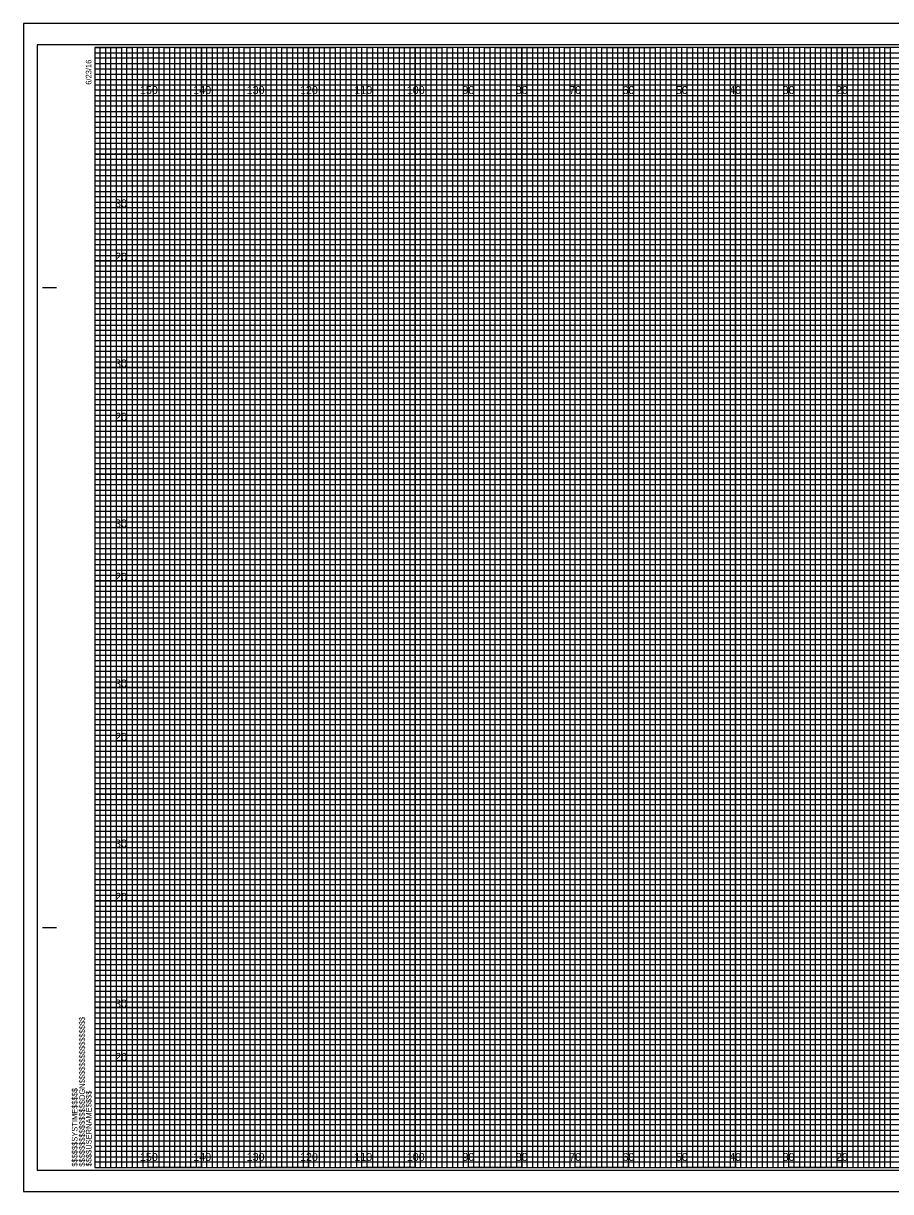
# Model space of a CAD drawing. Extents: x -13 to 323, y 1096 to 1314.
# Drawn here: x -13.4 to 149.1, y 1095.5 to 1314.5 of the extents above; entities that cross this region are included whole.
import ezdxf

# ---------------------------------------------------------------- set-up
doc = ezdxf.new("R2010")
doc.units = 0
for name, color, linetype in [('Prop XS Offset Labels', 7, 'Continuous'), ('Prop XS Station Labels', 7, 'Continuous'), ('Sheet Cross Section CELL', 7, 'Continuous'), ('Sheet Cross Section Grid Major CELL', 7, 'Continuous'), ('Sheet Cross Section Grid Middle CELL', 7, 'Continuous'), ('Sheet Cross Section Grid Minor 1 CELL', 7, 'Continuous'), ('Sheet Cross Section Grid Minor 2 CELL', 7, 'Continuous'), ('Sheet Cutting Line CELL', 7, 'Continuous'), ('Sheet DOT Grid CELL', 7, 'Continuous'), ('Sheet Plot Border Inside CELL', 7, 'Continuous'), ('Sheet Plot Border Outside CELL', 7, 'Continuous')]:
    doc.layers.add(name, color=color, linetype=linetype)

msp = doc.modelspace()

# ---------------------------------------------------------------- linework, layer by layer
at = {"layer": 'Sheet Cross Section CELL'}
for p, q in [((-9.8, 1265), (-7.3, 1265)), ((-9.7, 1265), (-7.2, 1265)), ((-9.8, 1145), (-7.3, 1145)), ((-9.7, 1145), (-7.2, 1145)), ((0, 1100), (0, 1100)), ((0, 1100), (0, 1100)), ((0, 1100), (0, 1100)), ((0, 1100), (0, 1100)), ((0, 1100), (0, 1100)), ((0, 1100), (0, 1100)), ((0, 1100), (0, 1100))]:
    msp.add_line(p, q, dxfattribs=at)
msp.add_lwpolyline([(320, 1310), (0, 1310), (0, 1100), (320, 1100)], close=True, dxfattribs=at)
at = {"layer": 'Sheet Cross Section Grid Major CELL'}
for p, q in [((10, 1310), (0, 1310)), ((10, 1100), (10, 1310)), ((30, 1310), (20, 1310)), ((20, 1310), (20, 1100)), ((30, 1100), (30, 1310)), ((50, 1310), (40, 1310)), ((40, 1310), (40, 1100)), ((50, 1100), (50, 1310)), ((70, 1310), (60, 1310)), ((60, 1310), (60, 1100)), ((70, 1100), (70, 1310)), ((90, 1310), (80, 1310)), ((80, 1310), (80, 1100)), ((90, 1100), (90, 1310)), ((110, 1310), (100, 1310)), ((100, 1310), (100, 1100)), ((110, 1100), (110, 1310)), ((130, 1310), (120, 1310)), ((120, 1310), (120, 1100)), ((130, 1100), (130, 1310)), ((150, 1310), (140, 1310)), ((140, 1310), (140, 1100)), ((20, 1100), (10, 1100)), ((40, 1100), (30, 1100)), ((60, 1100), (50, 1100)), ((80, 1100), (70, 1100)), ((100, 1100), (90, 1100)), ((120, 1100), (110, 1100)), ((140, 1100), (130, 1100))]:
    msp.add_line(p, q, dxfattribs=at)
for points in [[(0, 1300), (320, 1300), (320, 1290), (0, 1290)], [(0, 1280), (320, 1280), (320, 1270), (0, 1270)], [(0, 1260), (320, 1260), (320, 1250), (0, 1250)], [(0, 1240), (320, 1240), (320, 1230), (0, 1230)], [(0, 1220), (320, 1220), (320, 1210), (0, 1210)], [(0, 1200), (320, 1200), (320, 1190), (0, 1190)], [(0, 1180), (320, 1180), (320, 1170), (0, 1170)], [(0, 1160), (320, 1160), (320, 1150), (0, 1150)], [(0, 1140), (320, 1140), (320, 1130), (0, 1130)], [(0, 1120), (320, 1120), (320, 1110), (0, 1110)]]:
    msp.add_lwpolyline(points, dxfattribs=at)
at = {"layer": 'Sheet Cross Section Grid Middle CELL'}
for points in [[(0, 1310), (5, 1310), (5, 1100), (15, 1100), (15, 1310), (25, 1310), (25, 1100), (35, 1100), (35, 1310), (45, 1310), (45, 1100), (55, 1100), (55, 1310), (65, 1310), (65, 1100), (75, 1100), (75, 1310), (85, 1310), (85, 1100), (95, 1100), (95, 1310), (105, 1310), (105, 1100), (115, 1100), (115, 1310), (125, 1310), (125, 1100), (135, 1100), (135, 1310), (145, 1310), (145, 1100), (155, 1100)], [(0, 1305), (275, 1305)], [(0, 1285), (320, 1285), (320, 1295), (0, 1295)], [(0, 1265), (320, 1265), (320, 1275), (0, 1275)], [(0, 1245), (320, 1245), (320, 1255), (0, 1255)], [(0, 1225), (320, 1225), (320, 1235), (0, 1235)], [(0, 1205), (320, 1205), (320, 1215), (0, 1215)], [(0, 1185), (320, 1185), (320, 1195), (0, 1195)], [(0, 1165), (320, 1165), (320, 1175), (0, 1175)], [(0, 1145), (320, 1145), (320, 1155), (0, 1155)], [(0, 1125), (320, 1125), (320, 1135), (0, 1135)], [(0, 1105), (320, 1105), (320, 1115), (0, 1115)]]:
    msp.add_lwpolyline(points, dxfattribs=at)
at = {"layer": 'Sheet Cross Section Grid Minor 1 CELL'}
for p, q in [((0, 1309), (260, 1309)), ((260, 1307.98), (0, 1307.98)), ((0, 1307.98), (0, 1307)), ((0, 1307), (260, 1307)), ((260, 1305.89), (0, 1305.89)), ((0, 1305.89), (0, 1304)), ((0, 1304), (320, 1304))]:
    msp.add_line(p, q, dxfattribs=at)
for points in [[(0, 1303), (270, 1303), (320, 1303), (320, 1302), (0, 1302)], [(0, 1301), (320, 1301), (320, 1299), (0, 1299)], [(0, 1298), (320, 1298), (320, 1297), (0, 1296.98)], [(0, 1296), (320, 1296), (320, 1294), (0, 1294)], [(0, 1293), (320, 1293), (320, 1292), (0, 1292)], [(0, 1291), (320, 1291), (320, 1289), (0, 1289)], [(0, 1288), (320, 1288), (320, 1287), (0, 1287)], [(0, 1286), (320, 1286), (320, 1284), (0, 1284)], [(0, 1283), (320, 1283), (320, 1282), (0, 1282)], [(0, 1281), (320, 1281), (320, 1279), (0, 1279)], [(0, 1278), (320, 1278), (320, 1277), (0, 1277)], [(0, 1276), (320, 1276), (320, 1273.95), (320, 1273), (320, 1272), (0, 1272)], [(0, 1274), (320, 1274), (320, 1273), (0, 1273)], [(0, 1271), (320, 1271), (320, 1269), (0, 1269.03)], [(0, 1269.03), (320, 1269), (320, 1268), (0, 1268)], [(0, 1267), (320, 1267), (320, 1266), (0, 1266)], [(0, 1264), (320, 1264), (320, 1263), (0, 1263)], [(0, 1262), (320, 1262), (320, 1261), (0, 1261)], [(-0.07, 1258.89), (320, 1258.89), (320, 1257.88), (-0.07, 1257.88)], [(0, 1257), (320, 1257), (320, 1256), (0, 1256)], [(0, 1254), (320, 1254), (320, 1253), (0, 1253)], [(0, 1252), (320, 1252), (320, 1251), (0, 1251)], [(0, 1249), (320, 1249), (320, 1248), (0, 1248)], [(0, 1247), (320, 1247), (320, 1246), (0, 1246)], [(0, 1244), (320, 1244), (320, 1243), (0, 1243)], [(0, 1242), (320, 1242), (320, 1241), (0, 1241)], [(0, 1239), (320, 1239), (319.99, 1237.98), (0, 1238)], [(0, 1237), (320, 1237), (320, 1236), (0, 1236)], [(0, 1234), (320, 1234), (320, 1233), (0, 1233)], [(0, 1232), (320, 1232), (320, 1231), (0, 1231)], [(0, 1229), (320, 1229), (320, 1228), (0, 1228)], [(0, 1227), (320, 1227), (320, 1226), (0, 1226)], [(0, 1224), (320, 1224), (320, 1223), (0, 1223)], [(0, 1222), (320, 1222), (320, 1221), (0, 1221)], [(0, 1219), (320, 1219), (320, 1218), (0, 1218)], [(0, 1216.99), (320.07, 1216.91), (320, 1216), (0, 1216)], [(0, 1214), (320, 1214), (320, 1213), (0, 1213)], [(0, 1212), (320, 1212), (320, 1211), (0, 1211)], [(0, 1209), (320, 1209), (320, 1208), (0, 1208)], [(0, 1207), (320, 1207), (320, 1206), (0, 1206)], [(0, 1204), (320, 1204), (320, 1203), (0, 1203)], [(0, 1202), (320, 1202), (320, 1201), (0, 1201)], [(0, 1199), (320, 1199), (320, 1198), (0, 1198)], [(0, 1197), (320, 1197), (320, 1196), (0, 1196)], [(0, 1194), (320, 1194), (320, 1193), (0, 1193)], [(0, 1192), (320, 1192), (320, 1191), (0, 1191)], [(0, 1189), (320, 1189), (320, 1188), (0, 1188)], [(0, 1187), (320, 1187), (320, 1186), (0, 1186)], [(0, 1184), (320, 1184), (320, 1183), (0, 1183)], [(0, 1182), (320, 1182), (320, 1181), (0, 1181)], [(0, 1179), (320, 1179), (319.99, 1177.98), (0, 1178)], [(0, 1177), (320, 1177), (320, 1176), (0, 1176)], [(0, 1174), (320, 1174), (320, 1173), (0, 1173)], [(0, 1172), (320, 1172), (320, 1171), (0, 1171)], [(0, 1169), (320, 1169), (320, 1168), (0, 1168)], [(0, 1167), (320, 1167), (320, 1166), (0, 1166)], [(0, 1164), (320, 1164), (320, 1163), (0, 1163)], [(0, 1162), (320, 1162), (320, 1161), (0, 1161)], [(0, 1159), (320, 1159), (320, 1158), (0, 1158)], [(0, 1156.99), (320.07, 1156.91), (320, 1156), (0, 1156)], [(0, 1154), (320, 1154), (320, 1153), (0, 1153)], [(0, 1152), (320, 1152), (320, 1151), (0, 1151)], [(0, 1149), (320, 1149), (320, 1148), (0, 1148)], [(0, 1147), (320, 1147), (320, 1146), (0, 1146)], [(0, 1144), (320, 1144), (320, 1143), (0, 1143)], [(0, 1142), (320, 1142), (320, 1141), (0, 1141)], [(0, 1139), (320, 1139), (320, 1138), (0, 1138)], [(0, 1137), (320, 1137), (320, 1136), (0, 1136)], [(0, 1134), (320, 1134), (320, 1133), (0, 1133)], [(0, 1132), (320, 1132), (320, 1131), (0, 1131)], [(0, 1129), (320, 1129), (320, 1128), (0, 1128)], [(0, 1127), (320, 1127), (320, 1126), (0, 1126)], [(0, 1124), (320, 1124), (320, 1123), (0, 1123)], [(0, 1122), (320, 1122), (320, 1121), (0, 1121)], [(0, 1119), (320, 1119), (320, 1118), (0, 1118)], [(0, 1117), (320, 1117), (320, 1116), (0, 1116)], [(0, 1114), (320, 1114), (320, 1113), (0, 1113)], [(0, 1112), (320, 1112), (320, 1111), (0, 1111)], [(0, 1109), (320, 1109), (320, 1108), (0, 1108)], [(0, 1107), (320, 1107), (320, 1106), (0, 1106)], [(0, 1104), (320, 1104), (320, 1103), (0, 1103)], [(0, 1102), (320, 1102), (320, 1101), (0, 1101)]]:
    msp.add_lwpolyline(points, dxfattribs=at)
at = {"layer": 'Sheet Cross Section Grid Minor 2 CELL'}
for points in [[(0, 1100), (1, 1100), (1, 1310), (2, 1310), (2, 1100)], [(2, 1100), (3, 1100), (3, 1310), (4, 1310), (4, 1100)], [(5, 1100), (6, 1100), (6, 1310), (7, 1310), (7, 1100)], [(7, 1100), (8, 1100), (8, 1310), (9, 1310), (9, 1100)], [(10, 1100), (11, 1100), (11, 1310), (12, 1310), (12, 1100)], [(12, 1100), (13, 1100), (13, 1310), (14, 1310), (14, 1100)], [(15, 1100), (16, 1100), (16, 1310), (17, 1310), (17, 1100)], [(17, 1100), (18, 1100), (18, 1310), (19, 1310), (19, 1100)], [(20, 1100), (21, 1100), (21, 1310), (22, 1310), (22, 1100)], [(22, 1100), (23, 1100), (23, 1310), (24, 1310), (24, 1100)], [(25, 1100), (26, 1100), (26, 1310), (27, 1310), (27, 1100)], [(27, 1100), (28, 1100), (28, 1310), (29, 1310), (29, 1100)], [(30, 1100), (31, 1100), (31, 1310), (32, 1310), (32, 1100)], [(32, 1100), (33, 1100), (33, 1310), (34, 1310), (34, 1100)], [(35, 1100), (36, 1100), (36, 1310), (37, 1310), (37, 1100)], [(37, 1100), (38, 1100), (38, 1310), (39, 1310), (39, 1100)], [(40, 1100), (41, 1100), (41, 1310), (42, 1310), (42, 1100)], [(42, 1100), (43, 1100), (43, 1310), (44, 1310), (44, 1100)], [(45, 1100), (46, 1100), (46, 1310), (47, 1310), (47, 1100)], [(47, 1100), (48, 1100), (48, 1310), (49, 1310), (49, 1100)], [(50, 1100), (51, 1100), (51, 1310), (52, 1310), (52, 1100)], [(52, 1100), (53, 1100), (53, 1310), (54, 1310), (54, 1100)], [(55, 1100), (56, 1100), (56, 1310), (57, 1310), (57, 1100)], [(57, 1100), (58, 1100), (58, 1310), (59, 1310), (59, 1100)], [(60, 1100), (61, 1100), (61, 1310), (62, 1310), (62, 1100)], [(62, 1100), (63, 1100), (63, 1310), (64, 1310), (64, 1100)], [(65, 1100), (66, 1100), (66, 1310), (67, 1310), (67, 1100)], [(67, 1100), (68, 1100), (68, 1310), (69, 1310), (69, 1100)], [(70, 1100), (71, 1100), (71, 1310), (72, 1310), (72, 1100)], [(72, 1100), (73, 1100), (73, 1310), (74, 1310), (74, 1100)], [(75, 1100), (76, 1100), (76, 1310), (77, 1310), (77, 1100)], [(77, 1100), (78, 1100), (78, 1310), (79, 1310), (79, 1100)], [(80, 1100), (81, 1100), (81, 1310), (82, 1310), (82, 1100)], [(82, 1100), (83, 1100), (83, 1310), (84, 1310), (84, 1100)], [(85, 1100), (86, 1100), (86, 1310), (87, 1310), (87, 1100)], [(87, 1100), (88, 1100), (88, 1310), (89, 1310), (89, 1100)], [(90, 1100), (91, 1100), (91, 1310), (92, 1310), (92, 1100)], [(92, 1100), (93, 1100), (93, 1310), (94, 1310), (94, 1100)], [(95, 1100), (96, 1100), (96, 1310), (97, 1310), (97, 1100)], [(97, 1100), (98, 1100), (98, 1310), (99, 1310), (99, 1100)], [(100, 1100), (101, 1100), (101, 1310), (102, 1310), (102, 1100)], [(102, 1100), (103, 1100), (103, 1310), (104, 1310), (104, 1100)], [(105, 1100), (106, 1100), (106, 1310), (107, 1310), (107, 1100)], [(107, 1100), (108, 1100), (108, 1310), (109, 1310), (109, 1100)], [(110, 1100), (111, 1100), (111, 1310), (112, 1310), (112, 1100)], [(112, 1100), (113, 1100), (113, 1310), (114, 1310), (114, 1100)], [(115, 1100), (116, 1100), (116, 1310), (117, 1310), (117, 1100)], [(117, 1100), (118, 1100), (118, 1310), (119, 1310), (119, 1100)], [(120, 1100), (121, 1100), (121, 1310), (122, 1310), (122, 1100)], [(122, 1100), (123, 1100), (123, 1310), (124, 1310), (124, 1100)], [(125, 1100), (126, 1100), (126, 1310), (127, 1310), (127, 1100)], [(127, 1100), (128, 1100), (128, 1310), (129, 1310), (129, 1100)], [(130, 1100), (131, 1100), (131, 1310), (132, 1310), (132, 1100)], [(132, 1100), (133, 1100), (133, 1310), (134, 1310), (134, 1100)], [(135, 1100), (136, 1100), (136, 1310), (137, 1310), (137, 1100)], [(137, 1100), (138, 1100), (138, 1310), (139, 1310), (139, 1100)], [(140, 1100), (141, 1100), (141, 1310), (142, 1310), (142, 1100)], [(142, 1100), (143, 1100), (143, 1310), (144, 1310), (144, 1100)], [(145, 1100), (146, 1100), (146, 1310), (147, 1310), (147, 1100)], [(147, 1100), (148, 1100), (148, 1310), (149, 1310), (149, 1100)]]:
    msp.add_lwpolyline(points, dxfattribs=at)
at = {"layer": 'Sheet Cutting Line CELL'}
for p, q in [((323.3, 1314.5), (-13.4, 1314.5)), ((-13.4, 1314.5), (-13.4, 1095.5)), ((-13.4, 1095.5), (323.3, 1095.5))]:
    msp.add_line(p, q, dxfattribs=at)
at = {"layer": 'Sheet DOT Grid CELL'}
for p, q in [((10, 1100), (10, 1310)), ((20, 1100), (20, 1310)), ((30, 1100), (30, 1310)), ((40, 1100), (40, 1310)), ((50, 1100), (50, 1310)), ((60, 1100), (60, 1310)), ((70, 1100), (70, 1310)), ((80, 1100), (80, 1310)), ((90, 1100), (90, 1310)), ((100, 1100), (100, 1310)), ((110, 1100), (110, 1310)), ((120, 1100), (120, 1310)), ((130, 1100), (130, 1310)), ((140, 1100), (140, 1310)), ((0, 1300), (320, 1300)), ((0, 1290), (320, 1290)), ((0, 1280), (320, 1280)), ((0, 1270), (320, 1270)), ((0, 1260), (320, 1260)), ((0, 1250), (320, 1250)), ((0, 1240), (320, 1240)), ((0, 1230), (320, 1230)), ((0, 1220), (320, 1220)), ((0, 1210), (320, 1210)), ((0, 1200), (320, 1200)), ((0, 1190), (320, 1190)), ((0, 1180), (320, 1180)), ((0, 1170), (320, 1170)), ((0, 1160), (320, 1160)), ((0, 1150), (320, 1150)), ((0, 1140), (320, 1140)), ((0, 1130), (320, 1130)), ((0, 1120), (320, 1120)), ((0, 1110), (320, 1110))]:
    msp.add_line(p, q, dxfattribs=at)
at = {"layer": 'Sheet Plot Border Inside CELL'}
msp.add_lwpolyline([(-10.8, 1099.5), (322.4, 1099.5), (322.4, 1310.5), (-10.8, 1310.5)], close=True, dxfattribs=at)
at = {"layer": 'Sheet Plot Border Outside CELL'}
msp.add_lwpolyline([(-13.4, 1095.5), (323.3, 1095.5), (323.3, 1314.5), (-13.4, 1314.5)], close=True, dxfattribs=at)

# ---------------------------------------------------------------- texts
at = {"layer": 'Prop XS Offset Labels'}
for s, p in [('150', (8.44, 1301.25)), ('140', (18.44, 1301.25)), ('130', (28.44, 1301.25)), ('120', (38.44, 1301.25)), ('110', (48.62, 1301.25)), ('100', (58.44, 1301.25)), ('90', (68.86, 1301.25)), ('80', (78.86, 1301.25)), ('70', (88.86, 1301.25)), ('60', (98.86, 1301.25)), ('50', (108.86, 1301.25)), ('40', (118.86, 1301.25)), ('30', (128.86, 1301.25)), ('20', (138.86, 1301.25)), ('150', (8.44, 1101.25)), ('140', (18.44, 1101.25)), ('130', (28.44, 1101.25)), ('120', (38.44, 1101.25)), ('110', (48.62, 1101.25)), ('100', (58.44, 1101.25)), ('90', (68.86, 1101.25)), ('80', (78.86, 1101.25)), ('70', (88.86, 1101.25)), ('60', (98.86, 1101.25)), ('50', (108.86, 1101.25)), ('40', (118.86, 1101.25)), ('30', (128.86, 1101.25)), ('20', (138.86, 1101.25))]:
    msp.add_text(s, height=1.5, dxfattribs=at).set_placement(p)
at = {"layer": 'Prop XS Station Labels'}
for s, p in [('30', (3.78, 1280)), ('20', (3.8, 1270)), ('30', (3.78, 1250)), ('20', (3.8, 1240)), ('30', (3.78, 1220)), ('20', (3.8, 1210)), ('30', (3.78, 1190)), ('20', (3.8, 1180)), ('30', (3.78, 1160)), ('20', (3.8, 1150)), ('30', (3.78, 1130)), ('20', (3.8, 1120))]:
    msp.add_text(s, height=1.5, dxfattribs=at).set_placement(p)
at = {"layer": 'Sheet Cross Section CELL'}
for s, p in [('6/23/16', (-0.65, 1303)), ('$$$$$$$$$$$$$$$$DGN$$$$$$$$$$$$$$$$', (-1.88, 1100.18)), ('$$$$$$SYSTIME$$$$$', (-3.26, 1100.18)), ('$$$$USERNAME$$$$', (-0.62, 1100.23))]:
    msp.add_text(s, height=1.05, rotation=90, dxfattribs=at).set_placement(p)

doc.saveas('drawing.dxf')
